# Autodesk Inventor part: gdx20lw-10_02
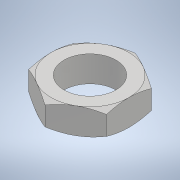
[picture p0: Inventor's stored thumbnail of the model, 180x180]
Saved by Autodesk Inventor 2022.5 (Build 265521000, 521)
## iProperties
Part Number: gdx20lw-10_02
Material: 一般
Document SubType Name: Modeling
Designer: ImaoCorp
Density: 1 g/cm^3
Appearance: 既定
Author: ImaoCorp
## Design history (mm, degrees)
feature "gdx20lw-10_02"
node "ソリッド1"
